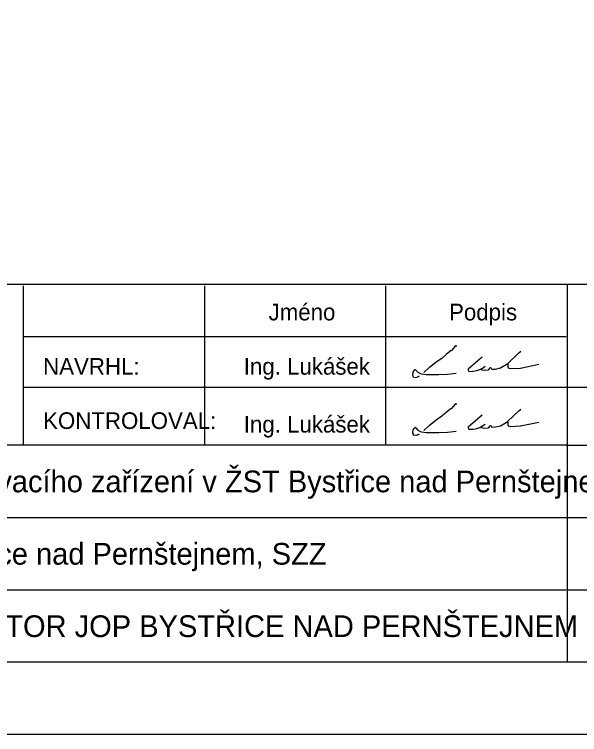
# Model space of a CAD drawing. Extents: x -1424 to 5155, y -2900 to 2050.
# Drawn here: x 3018.8 to 3096.8, y -2350 to -2250.5 of the extents above; entities that cross this region are included whole.
import ezdxf

# ---------------------------------------------------------------- set-up
doc = ezdxf.new("R2010")
doc.units = 0
doc.layers.add('Deska žb', color=7, linetype='Continuous')
doc.layers.add('Vrstva 1', color=7, linetype='Continuous')

msp = doc.modelspace()

# ---------------------------------------------------------------- linework, layer by layer
for p, q in [((3045, -2288), (3045, -2310)), ((3070, -2288), (3070, -2310)), ((3020, -2295), (3095, -2295)), ((3020, -2302), (3125, -2302)), ((3095, -2310), (3125, -2310)), ((2980, -2320), (3125, -2320)), ((2980, -2330), (3095, -2330))]:
    msp.add_line(p, q)
msp.add_lwpolyline([(2980, -2287.774), (3145, -2287.774), (3145, -2340), (2980, -2340)], close=True)
at = {"layer": 'Deska žb'}
for p, q in [((3079.661, -2296.336), (3079.119, -2296.937)), ((3079.713, -2296.306), (3079.686, -2296.318)), ((3079.822, -2296.4), (3079.818, -2296.366)), ((3078.467, -2297.453), (3077.795, -2298.022)), ((3079.11, -2296.945), (3078.469, -2297.452)), ((3086.943, -2298.71), (3088.453, -2297.26)), ((3088.459, -2297.255), (3088.727, -2297.047)), ((3077.788, -2298.027), (3077.012, -2298.549)), ((3083.372, -2297.859), (3081.473, -2299.461)), ((3076.03, -2299.334), (3075.31, -2299.965)), ((3077.007, -2298.553), (3076.033, -2299.332)), ((3083.045, -2299.556), (3083.4, -2299.364)), ((3083.404, -2299.362), (3083.808, -2299.107)), ((3084.28, -2299.579), (3084.474, -2299.344)), ((3084.598, -2299.357), (3084.659, -2299.472)), ((3085.23, -2299.496), (3085.888, -2299.336)), ((3085.909, -2299.327), (3086.929, -2298.721)), ((3086.922, -2298.731), (3086.922, -2299.191)), ((3086.933, -2299.231), (3087.008, -2299.349)), ((3087.061, -2299.383), (3087.336, -2299.422)), ((3087.35, -2299.423), (3088.645, -2299.363)), ((3088.657, -2299.362), (3091.209, -2298.821)), ((3073.793, -2300.325), (3073.848, -2299.911)), ((3073.868, -2300.601), (3073.795, -2300.356)), ((3073.864, -2299.873), (3074.073, -2299.617)), ((3074.179, -2299.607), (3074.207, -2299.63)), ((3074.215, -2299.638), (3074.474, -2299.926)), ((3074.492, -2299.94), (3074.658, -2300.037)), ((3074.668, -2300.042), (3074.956, -2300.157)), ((3074.972, -2300.161), (3075.65, -2300.265)), ((3077.372, -2300.265), (3078.602, -2300.205)), ((3078.606, -2300.205), (3079.777, -2300.085)), ((3081.447, -2299.518), (3081.447, -2299.597)), ((3081.448, -2299.61), (3081.467, -2299.729)), ((3081.532, -2299.791), (3081.71, -2299.813)), ((3081.725, -2299.814), (3082.106, -2299.784)), ((3082.111, -2299.784), (3082.641, -2299.71)), ((3082.658, -2299.706), (3083.036, -2299.56)), ((3083.221, -2299.513), (3083.249, -2299.559)), ((3083.301, -2299.594), (3083.619, -2299.647)), ((3083.636, -2299.648), (3084.227, -2299.606)), ((3084.727, -2299.512), (3085.214, -2299.499)), ((3074.104, -2300.697), (3073.922, -2300.652)), ((3074.366, -2300.644), (3074.139, -2300.698)), ((3074.663, -2300.476), (3074.387, -2300.636)), ((3079.661, -2304.336), (3079.119, -2304.937)), ((3079.713, -2304.306), (3079.686, -2304.318)), ((3079.822, -2304.4), (3079.818, -2304.366)), ((3079.11, -2304.945), (3078.469, -2305.452)), ((3086.943, -2306.71), (3088.453, -2305.26)), ((3088.459, -2305.255), (3088.727, -2305.047)), ((3077.788, -2306.027), (3077.012, -2306.549)), ((3078.467, -2305.453), (3077.795, -2306.022)), ((3083.372, -2305.859), (3081.473, -2307.461)), ((3076.03, -2307.334), (3075.31, -2307.965)), ((3077.007, -2306.553), (3076.033, -2307.332)), ((3083.045, -2307.556), (3083.4, -2307.364)), ((3083.404, -2307.362), (3083.808, -2307.107)), ((3084.28, -2307.579), (3084.474, -2307.344)), ((3084.598, -2307.357), (3084.659, -2307.472)), ((3085.23, -2307.496), (3085.888, -2307.336)), ((3085.909, -2307.327), (3086.929, -2306.721)), ((3086.922, -2306.731), (3086.922, -2307.191)), ((3086.933, -2307.231), (3087.008, -2307.349)), ((3087.061, -2307.383), (3087.336, -2307.422)), ((3087.35, -2307.423), (3088.645, -2307.363)), ((3088.657, -2307.362), (3091.209, -2306.821)), ((3073.793, -2308.325), (3073.848, -2307.911)), ((3073.868, -2308.601), (3073.795, -2308.356)), ((3073.864, -2307.873), (3074.073, -2307.617)), ((3074.179, -2307.607), (3074.207, -2307.63)), ((3074.215, -2307.638), (3074.474, -2307.926)), ((3074.492, -2307.94), (3074.658, -2308.037)), ((3074.668, -2308.042), (3074.956, -2308.157)), ((3074.972, -2308.161), (3075.65, -2308.265)), ((3077.372, -2308.265), (3078.602, -2308.205)), ((3078.606, -2308.205), (3079.777, -2308.085)), ((3081.447, -2307.518), (3081.447, -2307.597)), ((3081.448, -2307.61), (3081.467, -2307.729)), ((3081.532, -2307.791), (3081.71, -2307.813)), ((3081.725, -2307.814), (3082.106, -2307.784)), ((3082.111, -2307.784), (3082.641, -2307.71)), ((3082.658, -2307.706), (3083.036, -2307.56)), ((3083.221, -2307.513), (3083.249, -2307.559)), ((3083.301, -2307.594), (3083.619, -2307.647)), ((3083.636, -2307.648), (3084.227, -2307.606)), ((3084.727, -2307.512), (3085.214, -2307.499)), ((3074.104, -2308.697), (3073.922, -2308.652)), ((3074.366, -2308.644), (3074.139, -2308.698)), ((3074.663, -2308.476), (3074.387, -2308.636))]:
    msp.add_line(p, q, dxfattribs=at)
for points in [[(3075.661, -2300.265), (3076.408, -2300.265), (3077.368, -2300.265)], [(3075.661, -2308.265), (3076.408, -2308.265), (3077.368, -2308.265)]]:
    msp.add_lwpolyline(points, dxfattribs=at)
for centre, start, end in [((3079.717, -2296.387), 113.96249, 137.93567), ((3079.744, -2296.375), 6.34019, 113.96249), ((3078.516, -2297.511), 128.33334, 130.17923), ((3079.064, -2296.886), 308.33334, 317.93567), ((3088.505, -2297.314), 127.87498, 133.84267), ((3077.746, -2297.964), 303.94359, 310.17923), ((3076.08, -2299.39), 128.65981, 131.18593), ((3077.054, -2298.611), 123.94359, 128.65981), ((3083.364, -2299.298), 298.44293, 302.19573), ((3084.531, -2299.392), 27.89727, 140.44033), ((3085.87, -2299.263), 283.73627, 300.7189), ((3086.997, -2299.191), 180, 212.47119), ((3086.891, -2298.656), 300.7189, 313.84267), ((3087.072, -2299.309), 212.47119, 261.8699), ((3087.347, -2299.348), 261.8699, 272.63243), ((3088.642, -2299.288), 272.63243, 281.95658), ((3073.867, -2300.335), 172.40536, 196.69924), ((3073.922, -2299.92), 140.71059, 172.40536), ((3074.131, -2299.665), 50.19443, 140.71059), ((3074.159, -2299.688), 41.98721, 50.19443), ((3074.53, -2299.876), 221.98721, 239.74356), ((3074.696, -2299.972), 239.74356, 248.19859), ((3074.983, -2300.087), 248.19859, 261.34746), ((3075.661, -2300.19), 261.34746, 270), ((3077.368, -2300.19), 270, 272.7927), ((3078.598, -2300.13), 272.7927, 275.85601), ((3081.522, -2299.518), 130.156, 180), ((3081.522, -2299.597), 180, 189.46232), ((3081.541, -2299.717), 189.46232, 262.87498), ((3081.719, -2299.739), 262.87498, 274.39871), ((3082.1, -2299.71), 274.39871, 277.90716), ((3082.631, -2299.636), 277.90716, 291.03751), ((3083.01, -2299.49), 291.03751, 298.44293), ((3083.313, -2299.52), 210.96376, 260.53768), ((3083.631, -2299.573), 260.53768, 274.08562), ((3084.222, -2299.531), 274.08562, 320.44033), ((3084.725, -2299.437), 207.89727, 271.59114), ((3085.212, -2299.424), 271.59114, 283.73627), ((3073.94, -2300.579), 196.69924, 255.96376), ((3074.122, -2300.625), 255.96376, 283.24052), ((3074.349, -2300.571), 283.24052, 300.06858), ((3079.717, -2304.387), 113.96249, 137.93567), ((3079.744, -2304.375), 6.34019, 113.96249), ((3079.064, -2304.886), 308.33334, 317.93567), ((3088.505, -2305.314), 127.87498, 133.84267), ((3077.746, -2305.964), 303.94359, 310.17923), ((3078.516, -2305.511), 128.33334, 130.17923), ((3076.08, -2307.39), 128.65981, 131.18593), ((3077.054, -2306.611), 123.94359, 128.65981), ((3083.364, -2307.298), 298.44293, 302.19573), ((3084.531, -2307.392), 27.89727, 140.44033), ((3085.87, -2307.263), 283.73627, 300.7189), ((3086.997, -2307.191), 180, 212.47119), ((3086.891, -2306.656), 300.7189, 313.84267), ((3087.072, -2307.309), 212.47119, 261.8699), ((3088.642, -2307.288), 272.63243, 281.95658), ((3073.867, -2308.335), 172.40536, 196.69924), ((3073.922, -2307.92), 140.71059, 172.40536), ((3074.131, -2307.665), 50.19443, 140.71059), ((3074.159, -2307.688), 41.98721, 50.19443), ((3074.53, -2307.876), 221.98721, 239.74356), ((3074.696, -2307.972), 239.74356, 248.19859), ((3074.983, -2308.087), 248.19859, 261.34746), ((3075.661, -2308.19), 261.34746, 270), ((3077.368, -2308.19), 270, 272.7927), ((3078.598, -2308.13), 272.7927, 275.85601), ((3081.522, -2307.518), 130.156, 180), ((3081.522, -2307.597), 180, 189.46232), ((3081.541, -2307.717), 189.46232, 262.87498), ((3081.719, -2307.739), 262.87498, 274.39871), ((3082.1, -2307.71), 274.39871, 277.90716), ((3082.631, -2307.636), 277.90716, 291.03751), ((3083.01, -2307.49), 291.03751, 298.44293), ((3083.313, -2307.52), 210.96376, 260.53768), ((3083.631, -2307.573), 260.53768, 274.08562), ((3084.222, -2307.531), 274.08562, 320.44033), ((3084.725, -2307.437), 207.89727, 271.59114), ((3085.212, -2307.424), 271.59114, 283.73627), ((3087.347, -2307.348), 261.8699, 272.63243), ((3073.94, -2308.579), 196.69924, 255.96376), ((3074.122, -2308.625), 255.96376, 283.24052), ((3074.349, -2308.571), 283.24052, 300.06858)]:
    msp.add_arc(centre, 0.075, start, end, dxfattribs=at)
at = {"layer": 'Vrstva 1'}
for p, q in [((3020, -2310), (3020, -2288)), ((3095.12, -2287.706), (3095.12, -2340)), ((3095.12, -2310), (2980, -2310)), ((3095.12, -2330), (3145, -2330))]:
    msp.add_line(p, q, dxfattribs=at)
msp.add_lwpolyline([(3160, -2350), (2740, -2350), (2740, -2053), (3160, -2053)], close=True, dxfattribs=at)

# ---------------------------------------------------------------- texts
for s, height, p in [('Jméno', 2.3, (3053.87, -2292.774)), ('Podpis', 2.3, (3078.798, -2292.774)), ('NAVRHL:      ', 2.299, (3022.725, -2300.274)), ('Ing. Lukášek', 2.299, (3050.442, -2300.274)), ('KONTROLOVAL:', 2.299, (3022.725, -2307.774)), ('Ing. Lukášek', 2.299, (3050.442, -2308.274)), ('Oprava zabezpečovacího zařízení v ŽST Bystřice nad Pernštejnem', 3, (2982.725, -2316.524)), ('PS 06-28-01 Bystřice nad Pernštejnem, SZZ', 3, (2982.725, -2326.524)), ('POHLED NA MONITOR JOP BYSTŘICE NAD PERNŠTEJNEM', 3, (2982.725, -2336.524))]:
    msp.add_text(s, height=height).set_placement(p)

doc.saveas('drawing.dxf')
